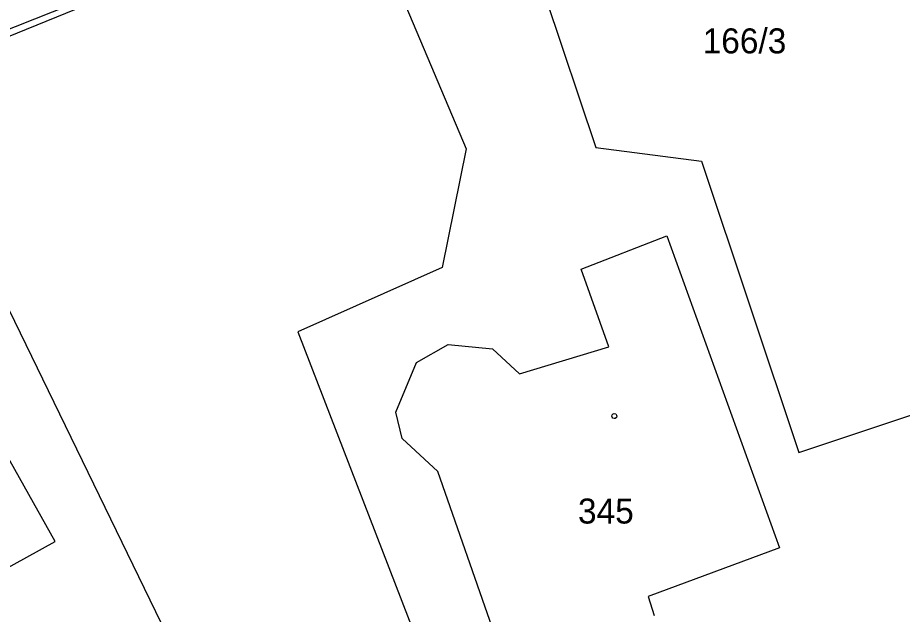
# Model space of a CAD drawing. Extents: x -757994 to -755874, y -1047691 to -1046119.
# Drawn here: x -756558.89 to -756528.82, y -1046667.8 to -1046647.52 of the extents above; entities that cross this region are included whole.
import ezdxf

# ---------------------------------------------------------------- set-up
doc = ezdxf.new("R2010")
doc.units = 0
doc.layers.add('g_plot', color=7, linetype='Continuous')
doc.layers.add('katastrální mapa', color=7, linetype='Continuous')

msp = doc.modelspace()

# ---------------------------------------------------------------- linework, layer by layer
at = {"layer": 'g_plot'}
msp.add_line((-756547.354, -1046643.338), (-756563.108, -1046649.75), dxfattribs=at)
at = {"layer": 'katastrální mapa'}
for p, q in [((-756542.79, -1046641.34), (-756539.24, -1046651.93)), ((-756547.35, -1046643.21), (-756563.08, -1046649.45)), ((-756547.35, -1046643.21), (-756543.65, -1046651.97)), ((-756543.65, -1046651.97), (-756544.46, -1046656.01)), ((-756539.24, -1046651.93), (-756535.65, -1046652.39)), ((-756535.65, -1046652.39), (-756532.34, -1046662.29)), ((-756539.74, -1046656.06), (-756536.82, -1046654.93)), ((-756536.82, -1046654.93), (-756532.99, -1046665.54)), ((-756560.21, -1046655.35), (-756531.49, -1046714.43)), ((-756544.46, -1046656.01), (-756549.37, -1046658.19)), ((-756538.8, -1046658.7), (-756539.74, -1046656.06)), ((-756549.37, -1046658.19), (-756543.7, -1046672.84)), ((-756545.33, -1046659.24), (-756544.26, -1046658.63)), ((-756544.26, -1046658.63), (-756542.75, -1046658.77)), ((-756541.83, -1046659.62), (-756538.8, -1046658.7)), ((-756542.75, -1046658.77), (-756541.83, -1046659.62)), ((-756546.04, -1046660.92), (-756545.33, -1046659.24)), ((-756532.34, -1046662.29), (-756524.8, -1046659.78)), ((-756545.82, -1046661.82), (-756546.04, -1046660.92)), ((-756544.61, -1046662.94), (-756545.82, -1046661.82)), ((-756542.29, -1046669.57), (-756544.61, -1046662.94)), ((-756532.99, -1046665.54), (-756537.46, -1046667.19)), ((-756537.46, -1046667.19), (-756537.25, -1046667.84))]:
    msp.add_line(p, q, dxfattribs=at)
msp.add_lwpolyline([(-756563.12, -1046665.74), (-756562.01, -1046667.75), (-756557.62, -1046665.32), (-756560.21, -1046660.71), (-756559.88, -1046660.52), (-756562.18, -1046656.43)], dxfattribs=at)
msp.add_lwpolyline([(-756538.61, -1046660.975), (-756538.56, -1046660.985), (-756538.535, -1046661.03), (-756538.525, -1046661.06), (-756538.535, -1046661.105), (-756538.575, -1046661.14), (-756538.61, -1046661.145), (-756538.655, -1046661.13), (-756538.685, -1046661.1), (-756538.695, -1046661.06), (-756538.685, -1046661.015), (-756538.645, -1046660.98)], close=True, dxfattribs=at)

# ---------------------------------------------------------------- texts
for s, p in [('166/3', (-756535.606, -1046648.73)), ('345', (-756539.844, -1046664.71))]:
    msp.add_text(s, height=0.85, dxfattribs=at).set_placement(p)

doc.saveas('drawing.dxf')
